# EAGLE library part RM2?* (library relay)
4 GHz 2 FORM C MICROWAVE RELAY NAiS Source: http://www.mew-europe.com/.. en_ds_61305_0000.pdf
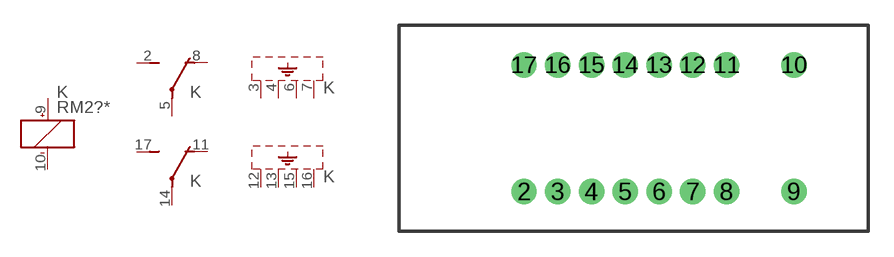
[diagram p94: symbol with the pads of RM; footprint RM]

Designator prefix K; gates A=K+- 1=U 2=U S1=SHIELD-4 S2=SHIELD-4

## RM2-3V (OC_FARNELL: unknown; OC_NEWARK: unknown), RM2-4.5V (OC_FARNELL: unknown; OC_NEWARK: unknown), RM2-5V (OC_FARNELL: unknown; OC_NEWARK: unknown), RM2-6V (OC_FARNELL: unknown; OC_NEWARK: unknown), RM2-9V (OC_FARNELL: unknown; OC_NEWARK: unknown), RM2-12V (OC_FARNELL: unknown; OC_NEWARK: unknown), RM2-24V (OC_FARNELL: unknown; OC_NEWARK: unknown)  [RM]
2  1:S  pas
3  S1:SH  pas
4  S1:SH  pas
5  1:P  pas
6  S1:SH  pas
7  S1:SH  pas
8  1:O  pas
9  A:+  pas
10  A:-  pas
11  2:O  pas
12  S2:SH  pas
13  S2:SH  pas
14  2:P  pas
15  S2:SH  pas
16  S2:SH  pas
17  2:S  pas

## RM2-L-3V (OC_FARNELL: unknown; OC_NEWARK: unknown), RM2-L-4.5V (OC_FARNELL: unknown; OC_NEWARK: unknown), RM2-L-5V (OC_FARNELL: unknown; OC_NEWARK: unknown), RM2-L-6V (OC_FARNELL: unknown; OC_NEWARK: unknown), RM2-L-9V (OC_FARNELL: unknown; OC_NEWARK: unknown), RM2-L-12V (OC_FARNELL: unknown; OC_NEWARK: unknown), RM2-L-24V (OC_FARNELL: unknown; OC_NEWARK: unknown)  [RM]
2  1:S  pas
3  S1:SH  pas
4  S1:SH  pas
5  1:P  pas
6  S1:SH  pas
7  S1:SH  pas
8  1:O  pas
9  A:-  pas
10  A:+  pas
11  2:O  pas
12  S2:SH  pas
13  S2:SH  pas
14  2:P  pas
15  S2:SH  pas
16  S2:SH  pas
17  2:S  pas

## Footprint RM (pad centres in mm)
4 GHz 2 FORM C MICROWAVE RELAY NAiS Source: http://www.mew-europe.com/.. en_ds_61305_0000.pdf
drill 1 round: 2 -6,-3.75; 3 -4,-3.75; 4 -2,-3.75; 5 0,-3.75; 6 2,-3.75; 7 4,-3.75; 8 6,-3.75; 9 10,-3.75; 10 10,3.75; 11 6,3.75; 12 4,3.75; 13 2,3.75; 14 0,3.75; 15 -2,3.75; 16 -4,3.75; 17 -6,3.75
